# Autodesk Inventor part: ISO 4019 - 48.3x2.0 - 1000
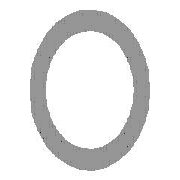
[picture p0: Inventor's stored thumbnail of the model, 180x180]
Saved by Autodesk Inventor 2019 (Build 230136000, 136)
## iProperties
_CCFamilyMember: 14
_CCFamilyDisplayName: ISO 4019 (Profils creux circulaires - Formés à froid) - Aciers de construction - Coupes creuses profilées formées à froid, soudées — ISO 4019 (Profils creux cir
_FrameMemberDoc: Frame Member File
_Version: 15.0.0
_GetPNFromCC: 1
Created: 2018-01
Part Number: ISO 4019 - 48.3x2.0 - 1000
Material: Acier, doux
Description: Aciers de construction - Coupes creuses profilées formées à froid, soudées
Document SubType Name: Modeling
Standard: ISO
Designer: Fabian Perrée
Standard Revision: Second edition 2001-09-01
Standards Organization: ISO
Language: fr-FR
Size Designation: 48.3x2.0
Categories: <MemberInstance><Categories><Category DisplayName="Profilés" InternalName="089c4875-fa83-4c05-b084-43b9cc11f5ed" Mnemonic="GRDR"><CategoryParameter DisplayName=
Stock Number: 48.3x2.0
Density: 7.85 g/cm^3
Appearance: Semi-poli
Mass: 2169.64 g
Surface Area: 2784 cm^2
Volume: 276.387 cm^3
IsCustomPart: 1
G_L: 1000,000 mm
G_W: 48,300 mm
G_H: 48,300 mm
+3083D47D-3926-4B9D-BF58-7B6EDEF830F9+DETAILDECOUPE1: Grugeage
+9EDA2250-0570-480B-9858-EB109F37A463+DETAILDECOUPE2: Grugeage
Author: Fabian Perrée
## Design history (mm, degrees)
node "Plan de départ"
node "Plan de fin"
sketch "Esquisse"
  geometry: C1 r 22.15 at (0, 0); C2 r 24.15 at (0, 0); 2 further points
  constraints: 3 coincident, 2 centre point
  dimensions: "d0" = 48.3 diameter of C2 (= G_H); "d1" = 2 radial gap between concentric circles of C2 C1 (= G_T)
extrude "Corps" new body sketch "Esquisse" stored distance "d2" = 1000 (= G_L); taper "d3" = 0 deg
node "Driven Length"
  sketch "Sketch3"
    geometry: L1 (0, 0)-(10, 0) reference
    constraints: 2 end point, 1 horizontal
  workplane "Work Plane3"
  sketch "Sketch4"
    geometry: L1 (-2, 0)-(12, 0) reference; L2 (-2, 1000)-(12, 1000) reference
    dimensions: "d7" = 1000 distance between parallel lines of L1 L2 (derived)
body "Solid1"
feature "Sculpter1"
feature "Combiner1"
feature "Sculpter3"
feature "Combiner3"
body "Srf29"
body "Srf30"
node "Solide11"
body "Srf32"
body "Srf33"
node "Solide12"
feature "Surface1"
body "Srf28"
feature "Carreau délimité19" dims "d44" = 5, "d45" = 0
feature "Carreau délimité20" dims "d46" = 5, "d47" = 0
feature "Surface3"
body "Srf31"
feature "Carreau délimité21" dims "d48" = 5, "d49" = 0
feature "Carreau délimité22" dims "d50" = 5, "d51" = 0
other parameters: "G_H" = 48.3 [user parameter; used in 1 equation term], "G_T" = 2 [user parameter; used in 1 equation term], "G_L" = 1000 (= d7) [user parameter; used in 1 equation term], "G_OFFSET_START" = 0 [user parameter; used in 1 equation term], "G_OFFSET_END" = 0 [user parameter; used in 1 equation term], "d4" = 0 (computed from G_OFFSET_START), "d5" = 1000 (= G_OFFSET_END + B_L), "B_L" = 1000 [user parameter; used in 1 equation term], "d6" = 90 deg, "MAS" = 0.228 [user parameter]
